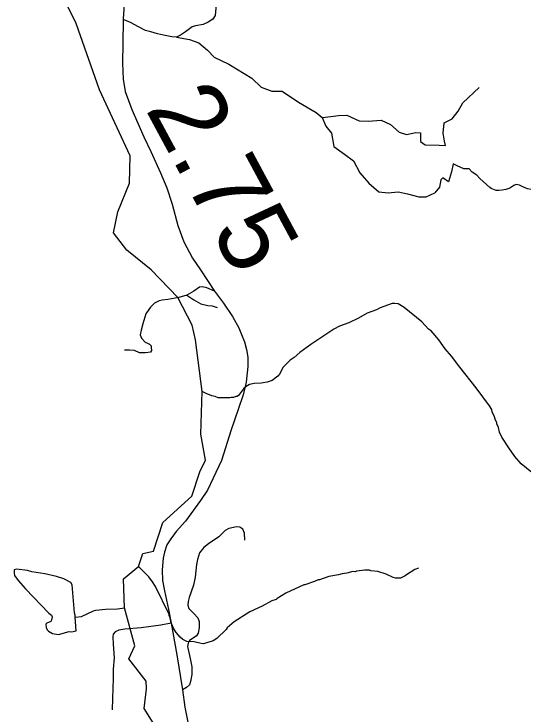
# Model space of a CAD drawing. Extents: x 1248089 to 1457196, y 820910 to 988753.
# Drawn here: x 1305675 to 1309100, y 844107 to 848812 of the extents above; entities that cross this region are included whole.
import ezdxf

# ---------------------------------------------------------------- set-up
doc = ezdxf.new("R2010")
doc.units = 0
for name, color, linetype in [('Exist Hydrographic Creek Single Shore', 7, 'Continuous'), ('Exist Hydrographic Misc Water Feature', 7, 'Continuous'), ('Exist Road Non-System Type 51', 7, 'Continuous'), ('Exist Road Secondary Type 51 Attributed', 7, 'Continuous'), ('Prop GRAU CAT1 Cell', 7, 'Continuous')]:
    doc.layers.add(name, color=color, linetype=linetype)

msp = doc.modelspace()

# ---------------------------------------------------------------- linework, layer by layer
at = {"layer": 'Exist Hydrographic Creek Single Shore'}
msp.add_lwpolyline([(1306620.9, 844029.8), (1306550, 844144.5), (1306563.8, 844277.6), (1306563.6, 844327.4), (1306446.3, 844477.5), (1306487.3, 844564.8), (1306416.5, 844820.1), (1306411, 845016.8), (1306511.9, 845098.7), (1306539.2, 845186.1), (1306612.8, 845202.5), (1306675.6, 845393.6), (1306868.8, 845571.5), (1306922.8, 845734.5), (1306962, 845813.9), (1306928.8, 845987.2), (1306938.5, 846275.7), (1306893.8, 846621.4), (1306870.7, 846720.3), (1306774.8, 846906.1), (1306595.8, 847093.5), (1306431.7, 847224.9), (1306343.8, 847341.5), (1306371.8, 847482.1), (1306450.7, 847674.2), (1306454.7, 847858), (1306248.7, 848302), (1306092.7, 848748.4), (1306004.7, 848927.4)], dxfattribs=at)
at = {"layer": 'Exist Hydrographic Misc Water Feature'}
for points in [[(1309189.8, 845701), (1309081.7, 845789.5), (1309038.9, 845838.5), (1308998.2, 845895.5), (1308951.8, 845968.5), (1308936.5, 846000.9), (1308929.3, 846033.1), (1308917.8, 846057.3), (1308918, 846065.3), (1308906.5, 846089.6), (1308902.9, 846105.6), (1308887.6, 846138), (1308883.9, 846154.1), (1308868.5, 846178.4), (1308779.3, 846300.5), (1308668.4, 846439.1), (1308614, 846512.4), (1308571.1, 846561.4), (1308528.5, 846622.3), (1308475.9, 846681.6), (1308460.1, 846693.9), (1308413.3, 846743), (1308295.4, 846839.8), (1308256, 846864.7), (1308232.1, 846867.3), (1308216, 846865.6), (1308133.4, 846837.6), (1308109.1, 846824.1), (1308046.5, 846801.6), (1307989.7, 846766.9), (1307925, 846736.5), (1307860.5, 846714), (1307822.1, 846692.9), (1307667.8, 846590.5), (1307594.5, 846536.3), (1307555.7, 846503.2), (1307529.4, 846485.8), (1307482.3, 846438.9), (1307457.2, 846391.5), (1307446.9, 846377.7), (1307408.3, 846348.6), (1307376, 846337.4), (1307335.8, 846330.3), (1307287.8, 846329.5), (1307255.6, 846322.2), (1307233.3, 846308.7), (1307217, 846293.2), (1307181.9, 846247.9), (1307173.8, 846242.2), (1307165.8, 846242.4), (1307149.6, 846234.7), (1307133.6, 846235.1), (1307125.5, 846231.3), (1307045.6, 846233.2), (1307026.4, 846242), (1307003.9, 846245.7), (1306966, 846261), (1306938.5, 846275.7)], [(1306086.2, 844757.9), (1306084.5, 844771.9), (1306080.9, 844788), (1306065.1, 844976.4), (1306055.5, 844990.6), (1306009.9, 845015.6), (1305960.3, 845030.8), (1305880.8, 845048.7), (1305795, 845062.7), (1305765.2, 845071.4), (1305691.4, 845081.1), (1305675.3, 845075.5), (1305674.8, 845053.5), (1305678.5, 845037.4), (1305701.7, 845004.9), (1305752.4, 844947.7), (1305908.7, 844786.1), (1305926.5, 844771.7), (1305932.2, 844759.5), (1305927.7, 844737.6), (1305921.6, 844729.8), (1305895.2, 844718.4), (1305889.1, 844710.5), (1305890.6, 844688.5), (1305898.2, 844672.3), (1305906, 844664.2), (1305933.7, 844647.5), (1305973.5, 844642.6), (1306045.9, 844660.9), (1306061.9, 844660.5), (1306092.5, 844666), (1306086.2, 844757.9)], [(1308391.8, 845087.8), (1308367.6, 845078.4), (1308310.8, 845043.7), (1308302.6, 845035.9), (1308270.3, 845020.7), (1308238.3, 845021.4), (1308222.3, 845025.8), (1308174.9, 845046.9), (1308119.2, 845064.2), (1308071.3, 845069.3), (1308063.4, 845073.5), (1308031.4, 845074.3), (1307975.4, 845067.6), (1307967.3, 845063.8), (1307951.3, 845064.1), (1307911, 845053.1), (1307878.9, 845049.8), (1307854.7, 845042.4), (1307790.5, 845031.9), (1307726, 845009.4), (1307718, 845009.6), (1307693.7, 844998.2), (1307629.2, 844975.7), (1307621.2, 844975.9), (1307499.9, 844918.7), (1307443.1, 844884.1), (1307434.9, 844876.3), (1307406.8, 844866.9), (1307342, 844832.5), (1307259.1, 844794.4), (1307153.5, 844726.9), (1307106.7, 844686), (1307100.4, 844676.2), (1307037, 844615.6), (1307012.6, 844598.3), (1306948.2, 844579.7), (1306932.2, 844580.1), (1306884.5, 844593.2), (1306836.5, 844594.4), (1306808.8, 844609), (1306791.2, 844623.4), (1306763.9, 844656), (1306748.4, 844680.4), (1306731.4, 844720.8), (1306724.1, 844753), (1306716.4, 844769.1), (1306716.6, 844777.1), (1306624.9, 844963.2), (1306605.6, 844995.7), (1306580.3, 845028.3), (1306511.9, 845098.7)], [(1306086.2, 844757.9), (1306128.3, 844762.9), (1306209.1, 844801), (1306225.2, 844804.6), (1306289.4, 844811.1), (1306369.4, 844813.3), (1306416.5, 844820.1)]]:
    msp.add_lwpolyline(points, dxfattribs=at)
at = {"layer": 'Exist Road Non-System Type 51'}
for points in [[(1307035.5, 848897.8), (1307025.3, 848802.9), (1307010.2, 848776.8), (1306979.8, 848757.1), (1306946.1, 848742.4), (1306893.9, 848732.6), (1306871.9, 848726.1), (1306826.4, 848693.4), (1306792.7, 848670.5), (1306765.7, 848657.4), (1306735.4, 848659), (1306678.1, 848670.5), (1306637.6, 848678.6), (1306593.8, 848691.7), (1306558.4, 848701.5), (1306511.2, 848726.1), (1306458.1, 848755.5), (1306408.1, 848775.2)], [(1306765.7, 848657.4), (1306852.9, 848641.2), (1306916.5, 848617.3), (1306974.8, 848569.6), (1307019.8, 848521.9), (1307117.8, 848474.2), (1307271.5, 848381.4), (1307335.1, 848320.4), (1307406.6, 848293.9), (1307475.5, 848293.9), (1307586.8, 848219.6), (1307703.4, 848150.7), (1307745.8, 848116.2)], [(1307745.8, 848116.2), (1307804.1, 848124.2), (1307854.4, 848129.5), (1307910.1, 848132.1), (1307992.2, 848095), (1308053.2, 848092.3), (1308140.6, 848097.6), (1308204.2, 848068.5), (1308262.5, 848018.1), (1308310.2, 848002.2), (1308373.8, 848015.4), (1308405.6, 848012.8), (1308405.6, 847954.5), (1308437.4, 847933.2), (1308530.1, 847930.6), (1308572.5, 847927.9), (1308567.2, 847957.1), (1308556.6, 848010.1), (1308564.5, 848081.7), (1308617.5, 848108.2), (1308657.3, 848158.6), (1308689.1, 848214.3), (1308800.4, 848317.7)], [(1307745.8, 848116.2), (1307769.6, 848057.9), (1307806.7, 848010.1), (1307822.6, 847922.6), (1307894.2, 847869.6), (1307955.1, 847824.5), (1307997.5, 847745), (1308058.5, 847676), (1308124.7, 847617.7), (1308188.3, 847609.7), (1308254.5, 847617.7), (1308318.1, 847604.4), (1308395, 847583.2), (1308442.7, 847583.2), (1308501, 847609.7)], [(1308870.4, 847646.5), (1308804.8, 847706.2), (1308783.6, 847730), (1308751.8, 847748.6), (1308733.3, 847772.5), (1308696.2, 847772.5), (1308651.2, 847791), (1308624.7, 847804.3), (1308614.1, 847751.3), (1308592.9, 847685), (1308555.8, 847711.5), (1308542.5, 847698.2), (1308531.9, 847647.8), (1308501, 847609.7)], [(1309180.6, 847635), (1309148.5, 847633.4), (1309124.9, 847636.7), (1309092.9, 847651.4), (1309069.3, 847662.8), (1309047.4, 847666.1), (1309032.2, 847659.6), (1309005.3, 847641.6), (1308978.3, 847631.8), (1308954.7, 847628.5), (1308931.1, 847626.9), (1308912.5, 847626.9), (1308880.5, 847639.9), (1308870.4, 847646.5)], [(1307021.1, 846949.7), (1306969.7, 846972.6), (1306941.1, 846979.1), (1306920.8, 846975.8), (1306882.1, 846949.7), (1306836.5, 846923.5)], [(1306836.5, 846923.5), (1306780.9, 846907.1), (1306708.4, 846892.4), (1306669.7, 846889.1), (1306649.4, 846884.2), (1306619.1, 846869.5), (1306592.1, 846841.7), (1306580.3, 846825.4), (1306560.1, 846795.9), (1306539.9, 846728.8), (1306528.1, 846687.9), (1306521.3, 846655.2), (1306531.4, 846632.3), (1306555, 846606.2), (1306571.9, 846599.6), (1306585.4, 846593.1), (1306595.5, 846581.6), (1306597.2, 846566.9), (1306598.9, 846555.5), (1306598.9, 846550.5), (1306592.1, 846539.1), (1306558.4, 846535.8), (1306517.9, 846534.2), (1306484.2, 846550.5), (1306450.5, 846553.8), (1306416.8, 846552.2)], [(1306836.5, 846923.5), (1306882.1, 846890.8), (1306929.3, 846864.6), (1306976.5, 846853.2), (1307006.8, 846851.5), (1307038.8, 846840.1)], [(1307226, 845274.7), (1307222.6, 845323.7), (1307210.8, 845349.9), (1307192.2, 845363), (1307168.6, 845364.6), (1307118.1, 845354.8), (1307092.8, 845341.7), (1307050.6, 845299.2), (1306981.5, 845251.8), (1306949.5, 845225.6), (1306920.8, 845191.3), (1306914.1, 845168.4), (1306907.3, 845145.5), (1306900.6, 845112.7), (1306892.2, 845027.7), (1306880.4, 844973.7), (1306851.7, 844890.3), (1306845, 844862.5), (1306843.3, 844837.9), (1306850, 844816.7), (1306883.7, 844782.3), (1306910.7, 844754.5), (1306919.1, 844728.3), (1306919.1, 844687.5), (1306912.4, 844651.5), (1306899.8, 844633.5), (1306877.8, 844617.1), (1306854.2, 844600.8), (1306844.1, 844582.8), (1306840.8, 844561.5), (1306857.6, 844481.3), (1306869.4, 844424.1), (1306869.4, 844373.4), (1306860.1, 844326), (1306853.4, 844303.1), (1306833.2, 844285.1), (1306806.2, 844268.7)], [(1306729.5, 844718.5), (1306661.2, 844705.4), (1306528.1, 844687.5), (1306418.5, 844677.6), (1306378, 844671.1), (1306354.4, 844659.6), (1306340.9, 844643.3), (1306339.3, 844625.3), (1306340.9, 844576.2), (1306347.7, 844484.6), (1306341.8, 844407.7), (1306340.1, 844345.6), (1306336.7, 844211.5), (1306333.4, 844134.6)]]:
    msp.add_lwpolyline(points, dxfattribs=at)
at = {"layer": 'Exist Road Secondary Type 51 Attributed'}
msp.add_lwpolyline([(1306418.5, 848937.1), (1306408.2, 848781.7), (1306408.1, 848775.2), (1306408, 848768.6), (1306405.8, 848618.1), (1306404.2, 848482.3), (1306407.5, 848374.4), (1306421, 848291), (1306466.5, 848169.9), (1306545.8, 847986.7), (1306593, 847888.6), (1306658.7, 847744.6), (1306700.8, 847643.2), (1306737.1, 847533.6), (1306775.9, 847389.7), (1306814.6, 847280.1), (1306872.8, 847172.1), (1306926.7, 847092), (1307021.1, 846949.7), (1307082.7, 846867.9), (1307141.7, 846777.9), (1307185.5, 846702.7), (1307204, 846658.5), (1307222.6, 846607.8), (1307236.1, 846557.1), (1307244.5, 846504.7), (1307246.2, 846442.6), (1307233.5, 846337.9), (1307213.3, 846252.8), (1307179.6, 846153.1), (1307132.4, 846017.3), (1307067.5, 845811.2), (1307011.9, 845691.8), (1306974.8, 845611.6), (1306927.6, 845542.9), (1306827.3, 845403.9), (1306763.2, 845333.6), (1306727.8, 845284.5), (1306700.8, 845243.6), (1306685.7, 845194.5), (1306677.2, 845155.3), (1306669.7, 845076.8), (1306673, 845004.8), (1306684.8, 844936.1), (1306711.8, 844810.1), (1306729.5, 844718.5), (1306768.3, 844504.2), (1306806.2, 844268.7), (1306823.1, 844154.2), (1306846.7, 844029.9)], dxfattribs=at)

# ---------------------------------------------------------------- texts
at = {"layer": 'Prop GRAU CAT1 Cell'}
msp.add_text('2.75', height=500, rotation=298.3118, dxfattribs=at).set_placement((1306553.9, 848174.8))

doc.saveas('drawing.dxf')
